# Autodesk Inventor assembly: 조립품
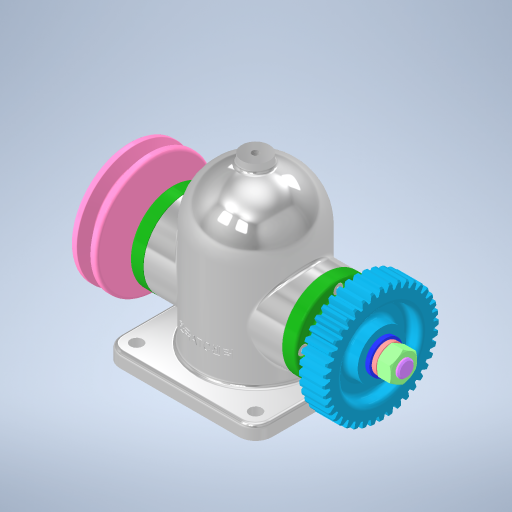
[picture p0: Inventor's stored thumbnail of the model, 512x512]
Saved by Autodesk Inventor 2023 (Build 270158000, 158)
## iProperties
Created: 2025-04
Part Number: 조립품
Document SubType Name: Assembly
Designer: ADMIN_PC
Author: ADMIN_PC
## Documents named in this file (14)
- C:\Users\ADMIN_PC\Downloads\750406V1006\조립품.iam
- C:\Users\ADMIN_PC\Downloads\750406V1006\본체.ipt
- C:\Users\ADMIN_PC\Downloads\750406V1006\깊은 홈 볼 베어링 6203.ipt
- C:\Users\ADMIN_PC\Downloads\750406V1006\축.ipt
- C:\Users\ADMIN_PC\Downloads\750406V1006\커버.ipt
- C:\Users\ADMIN_PC\Downloads\750406V1006\오일 실 26 38 8.ipt
- C:\Users\ADMIN_PC\Downloads\750406V1006\6각 구멍붙이 볼트 M4x12.ipt
- C:\Users\ADMIN_PC\Downloads\750406V1006\칼라.ipt
- C:\Users\ADMIN_PC\Downloads\750406V1006\평행 키 5x5x12.ipt
- C:\Users\ADMIN_PC\Downloads\750406V1006\스퍼기어.ipt
- C:\Users\ADMIN_PC\Downloads\750406V1006\V 벨트 풀리.ipt
- C:\Users\ADMIN_PC\Downloads\750406V1006\평와셔 M12.ipt
- C:\Users\ADMIN_PC\Downloads\750406V1006\스프링 와셔 M12.ipt
- C:\Users\ADMIN_PC\Downloads\750406V1006\6각 너트 M12x1.ipt
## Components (11 placed, 3 different names)
1. 6각 구멍붙이 볼트 M4x12:1
2. 6각 구멍붙이 볼트 M4x12:2
3. V 벨트 풀리:1
4. 6각 너트 M12x1:1
5. 6각 너트 M12x1:2
6. 6각 구멍붙이 볼트 M4x12:3
7. 6각 구멍붙이 볼트 M4x12:4
8. 6각 구멍붙이 볼트 M4x12:5
9. 6각 구멍붙이 볼트 M4x12:6
10. 6각 구멍붙이 볼트 M4x12:8
11. 6각 구멍붙이 볼트 M4x12:9
